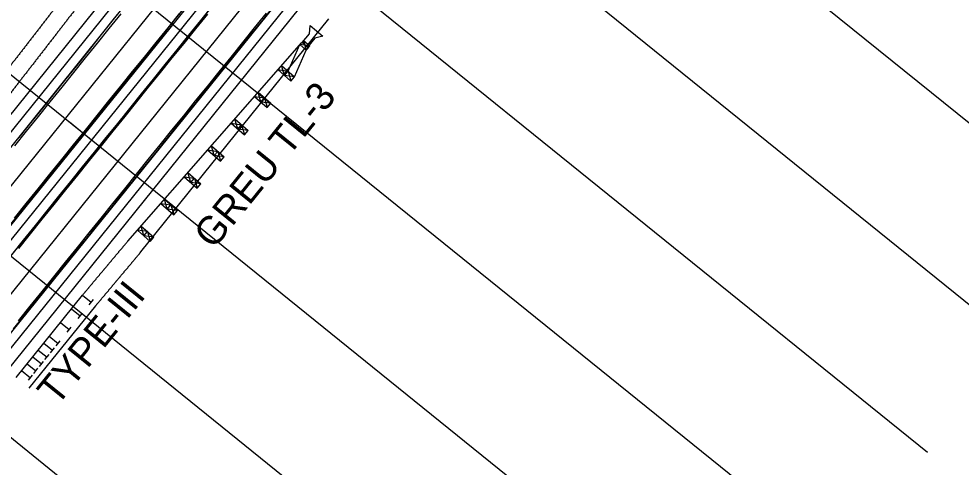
# Model space of a CAD drawing. Extents: x 2293233 to 2294507, y 892788 to 894229.
# Drawn here: x 2293993.2 to 2294160.2, y 893572.2 to 893651.6 of the extents above; entities that cross this region are included whole.
import ezdxf

# ---------------------------------------------------------------- set-up
doc = ezdxf.new("R2010")
doc.units = 0
for name, color, linetype in [('COGO Default Curve', 7, 'Continuous'), ('Prop EOT', 7, 'Continuous'), ('Prop Guardrail', 7, 'Continuous'), ('Prop Guardrail Anchor Unit CELL', 7, 'Continuous'), ('Prop Horizontal Alignment', 7, 'Continuous'), ('Prop Paved Shoulder', 7, 'Continuous'), ('Prop Structure Anchor Unit CELL', 7, 'Continuous'), ('Scratch_Level_4', 7, 'Continuous'), ('Scratch_Level_5', 7, 'Continuous')]:
    doc.layers.add(name, color=color, linetype=linetype)

msp = doc.modelspace()

# ---------------------------------------------------------------- linework, layer by layer
at = {"layer": 'COGO Default Curve'}
for p, q in [((2293758.37, 893332.69), (2294065.5, 893713.27)), ((2293767.71, 893325.15), (2294074.84, 893705.73))]:
    msp.add_line(p, q, dxfattribs=at)
for points in [[(2294153.14, 893810.31), (2294150.2, 893805.46), (2294144.41, 893796.11), (2294138.51, 893786.83), (2294132.51, 893777.61), (2294126.4, 893768.47), (2294120.19, 893759.4), (2294113.87, 893750.39), (2294110.57, 893745.78), (2294107.25, 893741.2), (2294103.51, 893736.09), (2294099.53, 893730.74), (2294095.52, 893725.42), (2294091.47, 893720.12), (2294087.39, 893714.85), (2294083.28, 893709.6), (2294078.73, 893703.85), (2294073.94, 893697.86), (2293868.79, 893443.63)], [(2293934.91, 893558.24), (2293982.19, 893616.89), (2294012.67, 893654.83), (2294024.95, 893670.19), (2294035.75, 893683.75), (2294045.26, 893695.77), (2294053.92, 893706.78), (2294061.7, 893716.77), (2294068.83, 893726.01), (2294075.49, 893734.76), (2294081.7, 893743.02), (2294085.47, 893748.1), (2294089.22, 893753.21), (2294092.74, 893758.07), (2294096.24, 893762.94), (2294099.7, 893767.84), (2294102.95, 893772.49), (2294106.35, 893777.42), (2294109.73, 893782.38), (2294113.08, 893787.36), (2294116.39, 893792.36), (2294119.68, 893797.38), (2294123.12, 893802.7), (2294126.34, 893807.75)], [(2294137.26, 893807.39), (2294131.61, 893798.35), (2294125.85, 893789.36), (2294119.8, 893780.17), (2294113.84, 893771.33), (2294107.78, 893762.55), (2294101.61, 893753.84), (2294095.16, 893744.94), (2294091.39, 893739.84), (2294087.6, 893734.78), (2294083.76, 893729.73), (2294079.69, 893724.45), (2294075.59, 893719.2), (2294071.04, 893713.45), (2294059.17, 893698.61), (2294044.74, 893680.7), (2293954.06, 893568.41)], [(2293932.89, 893536.61), (2294046.75, 893677.72), (2294053.42, 893686.04), (2294059.44, 893693.61), (2294065.01, 893700.68), (2294070.34, 893707.51), (2294075.44, 893714.1), (2294080.29, 893720.46), (2294085.11, 893726.85), (2294089.69, 893733), (2294096.97, 893742.96), (2294103.95, 893752.72), (2294107.4, 893757.63), (2294110.82, 893762.56), (2294114.21, 893767.5), (2294117.58, 893772.47), (2294120.92, 893777.46), (2294124.04, 893782.19), (2294127.32, 893787.21), (2294130.39, 893791.98), (2294133.61, 893797.04), (2294136.62, 893801.84), (2294139.78, 893806.94)], [(2294022.82, 893653.91), (2294020.74, 893651.3), (2294018.65, 893648.7), (2294016.57, 893646.1), (2294014.48, 893643.5), (2294012.39, 893640.9), (2294010.31, 893638.3), (2294008.22, 893635.7), (2294006.13, 893633.1), (2294004.04, 893630.5), (2294001.95, 893627.9), (2293999.86, 893625.3), (2293997.77, 893622.7), (2293995.69, 893620.1), (2293993.6, 893617.51), (2293991.5, 893614.91)], [(2293991.98, 893609.83), (2293994.07, 893612.42), (2293996.17, 893615.01), (2293998.26, 893617.61), (2294000.35, 893620.2), (2294002.45, 893622.8), (2294004.54, 893625.39), (2294006.63, 893627.99), (2294008.73, 893630.58), (2294010.82, 893633.17), (2294012.91, 893635.77), (2294015.01, 893638.36), (2294017.1, 893640.96), (2294019.2, 893643.55), (2294021.29, 893646.15), (2294023.38, 893648.74), (2294025.48, 893651.33), (2294027.57, 893653.93)], [(2293992.31, 893596.7), (2293994.41, 893599.3), (2293996.5, 893601.89), (2293998.59, 893604.49), (2294000.69, 893607.08), (2294002.78, 893609.68), (2294004.87, 893612.27), (2294006.97, 893614.86), (2294009.06, 893617.46), (2294011.15, 893620.05), (2294013.25, 893622.65), (2294015.34, 893625.24), (2294017.44, 893627.84), (2294019.53, 893630.43), (2294021.62, 893633.02), (2294023.72, 893635.62), (2294025.81, 893638.21), (2294027.9, 893640.81), (2294030, 893643.4), (2294032.09, 893646), (2294034.18, 893648.59), (2294036.28, 893651.18), (2294038.37, 893653.78)], [(2294012.02, 893654.02), (2294009.93, 893651.42), (2294007.85, 893648.82), (2294005.76, 893646.22), (2294003.68, 893643.62), (2294001.59, 893641.02), (2293999.5, 893638.42), (2293997.42, 893635.82), (2293995.33, 893633.22), (2293993.24, 893630.63)], [(2294021.72, 893652.65), (2294019.62, 893650.05), (2294017.53, 893647.46), (2294015.44, 893644.86), (2294013.34, 893642.27), (2294011.25, 893639.67), (2294009.16, 893637.08), (2294007.06, 893634.49), (2294004.97, 893631.89), (2294002.87, 893629.3), (2294000.78, 893626.7), (2293998.69, 893624.11), (2293996.59, 893621.51), (2293994.5, 893618.92), (2293992.41, 893616.33)], [(2294011.3, 893652.48), (2294009.21, 893649.89), (2294007.12, 893647.29), (2294005.02, 893644.7), (2294002.93, 893642.1), (2294000.84, 893639.51), (2293998.74, 893636.91), (2293996.65, 893634.32), (2293994.55, 893631.73), (2293992.46, 893629.13)], [(2293993.16, 893598.15), (2293995.25, 893600.75), (2293997.35, 893603.34), (2293999.44, 893605.94), (2294001.53, 893608.53), (2294003.63, 893611.12), (2294005.72, 893613.72), (2294007.82, 893616.31), (2294009.91, 893618.91), (2294012, 893621.5), (2294014.1, 893624.1), (2294016.19, 893626.69), (2294018.28, 893629.28), (2294020.38, 893631.88), (2294022.47, 893634.47), (2294024.56, 893637.07), (2294026.66, 893639.66), (2294028.75, 893642.26), (2294030.85, 893644.85), (2294032.94, 893647.44), (2294035.03, 893650.04), (2294037.13, 893652.63)], [(2293993.22, 893610.96), (2293995.31, 893613.55), (2293997.4, 893616.15), (2293999.5, 893618.74), (2294001.59, 893621.34), (2294003.68, 893623.93), (2294005.78, 893626.53), (2294007.87, 893629.12), (2294009.96, 893631.71), (2294012.06, 893634.31), (2294014.15, 893636.9), (2294016.25, 893639.5), (2294018.34, 893642.09), (2294020.43, 893644.69), (2294022.53, 893647.28), (2294024.62, 893649.87), (2294026.71, 893652.47)]]:
    msp.add_lwpolyline(points, dxfattribs=at)
at = {"layer": 'Prop EOT'}
for p, q in [((2293753.7, 893336.46), (2294060.83, 893717.04)), ((2293753.7, 893336.46), (2294060.83, 893717.04)), ((2293772.37, 893321.38), (2294079.51, 893701.97))]:
    msp.add_line(p, q, dxfattribs=at)
at = {"layer": 'Prop Guardrail'}
for points in [[(2294010.25, 893662.32), (2294009.84, 893661.79), (2294009.42, 893661.25), (2294009.01, 893660.72), (2294008.6, 893660.19), (2294008.18, 893659.65), (2294007.77, 893659.12), (2294007.35, 893658.58), (2294006.94, 893658.05), (2294006.53, 893657.51), (2294006.11, 893656.98), (2294005.7, 893656.45), (2294005.29, 893655.91), (2294004.87, 893655.38), (2294004.46, 893654.84), (2294004.04, 893654.31), (2294003.63, 893653.77), (2294003.22, 893653.24), (2294002.8, 893652.71), (2294002.39, 893652.17), (2294001.97, 893651.64), (2294001.56, 893651.1), (2294001.15, 893650.57), (2294000.73, 893650.03), (2294000.32, 893649.5), (2293999.91, 893648.97), (2293999.49, 893648.43), (2293999.08, 893647.9), (2293998.66, 893647.36), (2293998.25, 893646.83), (2293997.84, 893646.29), (2293997.42, 893645.76), (2293997.01, 893645.23), (2293996.59, 893644.69), (2293996.18, 893644.16), (2293995.77, 893643.62), (2293995.35, 893643.09), (2293994.94, 893642.55), (2293994.53, 893642.02), (2293994.11, 893641.49), (2293993.7, 893640.95), (2293993.28, 893640.42), (2293992.87, 893639.88), (2293992.46, 893639.35), (2293992.04, 893638.81), (2293991.63, 893638.28), (2293991.22, 893637.75), (2293990.8, 893637.21), (2293990.39, 893636.68), (2293989.97, 893636.14), (2293989.56, 893635.61), (2293989.15, 893635.07), (2293988.73, 893634.54), (2293988.32, 893634.01), (2293987.9, 893633.47), (2293987.49, 893632.94), (2293987.08, 893632.4), (2293986.66, 893631.87), (2293986.25, 893631.33), (2293985.84, 893630.8), (2293985.42, 893630.27), (2293985.01, 893629.73), (2293984.59, 893629.2), (2293984.18, 893628.66), (2293983.77, 893628.13), (2293983.35, 893627.59), (2293982.94, 893627.06), (2293982.53, 893626.52), (2293982.11, 893625.99), (2293981.7, 893625.46), (2293981.28, 893624.92), (2293980.87, 893624.39), (2293980.46, 893623.85), (2293980.04, 893623.32), (2293979.63, 893622.78)], [(2294004.53, 893602.69), (2294004.64, 893602.82), (2294004.75, 893602.95), (2294004.86, 893603.08), (2294004.97, 893603.21), (2294005.07, 893603.33), (2294005.18, 893603.46), (2294005.29, 893603.59), (2294005.4, 893603.72), (2294005.51, 893603.85), (2294005.62, 893603.98), (2294005.73, 893604.11), (2294005.84, 893604.24), (2294005.94, 893604.37), (2294006.05, 893604.5), (2294006.16, 893604.63), (2294006.27, 893604.76), (2294006.38, 893604.89), (2294006.49, 893605.02), (2294006.6, 893605.15), (2294006.71, 893605.27), (2294006.81, 893605.4), (2294006.92, 893605.53), (2294007.03, 893605.66), (2294007.14, 893605.79), (2294007.25, 893605.92), (2294007.36, 893606.05), (2294007.47, 893606.18), (2294007.57, 893606.31), (2294007.68, 893606.44), (2294007.79, 893606.57), (2294007.9, 893606.7), (2294008.01, 893606.83), (2294008.12, 893606.96), (2294008.23, 893607.09), (2294008.34, 893607.21), (2294008.44, 893607.34), (2294008.55, 893607.47), (2294008.66, 893607.6), (2294008.77, 893607.73), (2294008.88, 893607.86), (2294008.99, 893607.99), (2294009.1, 893608.12), (2294009.21, 893608.25), (2294009.31, 893608.38), (2294009.42, 893608.51), (2294009.53, 893608.64), (2294009.64, 893608.77), (2294009.75, 893608.9), (2294009.86, 893609.03), (2294009.97, 893609.15), (2294010.08, 893609.28), (2294010.18, 893609.41), (2294010.29, 893609.54), (2294010.4, 893609.67), (2294010.51, 893609.8), (2294010.62, 893609.93), (2294010.73, 893610.06), (2294010.84, 893610.19), (2294010.94, 893610.32), (2294011.05, 893610.45), (2294011.16, 893610.58), (2294011.27, 893610.71), (2294011.38, 893610.84), (2294011.49, 893610.97), (2294011.6, 893611.09), (2294011.71, 893611.22), (2294011.81, 893611.35), (2294011.92, 893611.48), (2294012.03, 893611.61), (2294012.14, 893611.74), (2294012.25, 893611.87), (2294012.36, 893612), (2294012.58, 893612.26)]]:
    msp.add_spline(points, degree=3, dxfattribs=at)
at = {"layer": 'Prop Guardrail Anchor Unit CELL'}
for p, q in [((2294044.77, 893648.98), (2294044.87, 893650.43)), ((2294044.87, 893650.43), (2294047.11, 893648.54)), ((2294043.45, 893647.41), (2294044.77, 893648.98)), ((2294047.11, 893648.54), (2294045.7, 893648.19)), ((2294012.58, 893612.26), (2294043.37, 893647.44)), ((2294040.96, 893642.36), (2294043.04, 893647.06)), ((2294043.04, 893647.06), (2294044.17, 893646.07)), ((2294044.83, 893646.83), (2294043.04, 893647.06)), ((2294043.91, 893647.02), (2294043.45, 893647.41)), ((2294043.7, 893647.81), (2294044.83, 893646.83)), ((2294043.7, 893647.81), (2294044.17, 893646.07)), ((2294044.38, 893646.62), (2294043.91, 893647.02)), ((2294045.7, 893648.19), (2294044.38, 893646.62)), ((2294042.12, 893641.36), (2294044.17, 893646.07)), ((2294044.17, 893646.07), (2294044.83, 893646.83)), ((2294044.17, 893646.07), (2294044.5, 893646.45)), ((2294039.15, 893642.62), (2294041.46, 893640.6)), ((2294039.15, 893642.62), (2294040.96, 893642.36)), ((2294039.81, 893643.37), (2294042.12, 893641.36)), ((2294040.3, 893641.61), (2294039.81, 893643.37)), ((2294040.3, 893641.61), (2294040.96, 893642.36)), ((2294040.96, 893642.36), (2294041.46, 893640.6)), ((2294042.12, 893641.36), (2294040.3, 893641.61)), ((2294041.46, 893640.6), (2294042.12, 893641.36)), ((2294035.66, 893638.63), (2294037.92, 893636.66)), ((2294036.13, 893636.89), (2294035.66, 893638.63)), ((2294035, 893637.88), (2294037.26, 893635.9)), ((2294035, 893637.88), (2294036.79, 893637.64)), ((2294036.13, 893636.89), (2294036.79, 893637.64)), ((2294037.92, 893636.66), (2294036.13, 893636.89)), ((2294036.79, 893637.64), (2294037.26, 893635.9)), ((2294037.26, 893635.9), (2294037.92, 893636.66)), ((2294031.51, 893633.89), (2294033.87, 893631.82)), ((2294032.03, 893632.1), (2294031.51, 893633.89)), ((2294030.85, 893633.14), (2294033.21, 893631.07)), ((2294030.85, 893633.14), (2294032.69, 893632.86)), ((2294032.03, 893632.1), (2294032.69, 893632.86)), ((2294033.87, 893631.82), (2294032.03, 893632.1)), ((2294032.69, 893632.86), (2294033.21, 893631.07)), ((2294033.21, 893631.07), (2294033.87, 893631.82)), ((2294026.7, 893628.4), (2294027.36, 893629.15)), ((2294027.36, 893629.15), (2294029.64, 893627.15)), ((2294027.84, 893627.4), (2294027.36, 893629.15)), ((2294026.7, 893628.4), (2294028.98, 893626.4)), ((2294026.7, 893628.4), (2294028.5, 893628.15)), ((2294027.84, 893627.4), (2294028.5, 893628.15)), ((2294029.64, 893627.15), (2294027.84, 893627.4)), ((2294028.5, 893628.15), (2294028.98, 893626.4)), ((2294028.98, 893626.4), (2294029.64, 893627.15)), ((2294022.55, 893623.65), (2294024.84, 893621.65)), ((2294022.55, 893623.65), (2294024.36, 893623.4)), ((2294023.21, 893624.41), (2294025.5, 893622.4)), ((2294023.7, 893622.65), (2294023.21, 893624.41)), ((2294023.7, 893622.65), (2294024.36, 893623.4)), ((2294025.5, 893622.4), (2294023.7, 893622.65)), ((2294024.36, 893623.4), (2294024.84, 893621.65)), ((2294024.84, 893621.65), (2294025.5, 893622.4)), ((2294018.4, 893618.91), (2294020.7, 893616.9)), ((2294018.4, 893618.91), (2294020.21, 893618.66)), ((2294019.06, 893619.67), (2294021.36, 893617.66)), ((2294019.55, 893617.91), (2294019.06, 893619.67)), ((2294019.55, 893617.91), (2294020.21, 893618.66)), ((2294020.21, 893618.66), (2294020.7, 893616.9)), ((2294021.36, 893617.66), (2294019.55, 893617.91)), ((2294020.7, 893616.9), (2294021.36, 893617.66)), ((2294014.25, 893614.17), (2294014.91, 893614.92)), ((2294014.25, 893614.17), (2294016.51, 893612.2)), ((2294016.04, 893613.94), (2294014.25, 893614.17)), ((2294014.91, 893614.92), (2294017.17, 893612.95)), ((2294014.91, 893614.92), (2294016.04, 893613.94)), ((2294015.38, 893613.18), (2294014.91, 893614.92)), ((2294015.38, 893613.18), (2294016.04, 893613.94)), ((2294016.04, 893613.94), (2294016.51, 893612.2)), ((2294017.17, 893612.95), (2294015.38, 893613.18)), ((2294016.51, 893612.2), (2294017.17, 893612.95))]:
    msp.add_line(p, q, dxfattribs=at)
at = {"layer": 'Prop Horizontal Alignment'}
for p, q in [((2293763.04, 893328.92), (2294070.17, 893709.5)), ((2293763.04, 893328.92), (2294070.17, 893709.5)), ((2294006.14, 893630.16), (2294002.25, 893633.3))]:
    msp.add_line(p, q, dxfattribs=at)
at = {"layer": 'Prop Paved Shoulder'}
for p, q in [((2293752.14, 893337.71), (2294059.27, 893718.29)), ((2293773.93, 893320.13), (2294081.06, 893700.71))]:
    msp.add_line(p, q, dxfattribs=at)
at = {"layer": 'Prop Structure Anchor Unit CELL'}
for p, q in [((2293992.76, 893588.1), (2294004.53, 893602.69)), ((2294004.53, 893602.69), (2294006.09, 893601.43)), ((2294005.73, 893600.99), (2294006.45, 893601.88)), ((2294002.57, 893600.26), (2294004.12, 893599)), ((2294003.76, 893598.55), (2294004.48, 893599.45)), ((2294000.61, 893597.82), (2294002.16, 893596.57)), ((2294001.8, 893596.12), (2294002.52, 893597.01)), ((2293998.64, 893595.39), (2294000.2, 893594.14)), ((2293997.66, 893594.18), (2293999.22, 893592.92)), ((2293999.84, 893593.69), (2294000.56, 893594.58)), ((2293996.68, 893592.96), (2293998.24, 893591.7)), ((2293997.88, 893591.26), (2293998.6, 893592.15)), ((2293998.86, 893592.47), (2293999.58, 893593.37)), ((2293994.72, 893590.53), (2293996.27, 893589.27)), ((2293995.7, 893591.74), (2293997.26, 893590.49)), ((2293996.9, 893590.04), (2293997.62, 893590.93)), ((2293993.74, 893589.31), (2293995.29, 893588.06)), ((2293994.93, 893587.61), (2293995.65, 893588.5)), ((2293995.91, 893588.83), (2293996.63, 893589.72))]:
    msp.add_line(p, q, dxfattribs=at)
at = {"layer": 'Scratch_Level_4'}
for p, q in [((2293952.21, 893802.18), (2294185.67, 893613.78)), ((2293708.32, 893261.12), (2294130.82, 893784.65)), ((2293936.51, 893782.73), (2294169.97, 893594.32)), ((2293920.81, 893763.27), (2294154.27, 893574.87)), ((2293905.11, 893743.82), (2294138.57, 893555.41)), ((2293889.41, 893724.36), (2294122.87, 893535.96)), ((2293873.71, 893704.91), (2294107.17, 893516.5)), ((2293858.01, 893685.45), (2294091.47, 893497.05))]:
    msp.add_line(p, q, dxfattribs=at)
at = {"layer": 'Scratch_Level_5'}
for p, q in [((2294014.87, 893610.33), (2294048.19, 893651.62)), ((2293995.09, 893586.21), (2294006.87, 893600.8))]:
    msp.add_line(p, q, dxfattribs=at)
for points in [[(2294007.88, 893664.16), (2294007.47, 893663.63), (2294007.05, 893663.09), (2294006.64, 893662.56), (2294006.22, 893662.02), (2294005.81, 893661.49), (2294005.4, 893660.95), (2294004.98, 893660.42), (2294004.57, 893659.89), (2294004.15, 893659.35), (2294003.74, 893658.82), (2294003.33, 893658.28), (2294002.91, 893657.75), (2294002.5, 893657.21), (2294002.09, 893656.68), (2294001.67, 893656.15), (2294001.26, 893655.61), (2294000.84, 893655.08), (2294000.43, 893654.54), (2294000.02, 893654.01), (2293999.6, 893653.47), (2293999.19, 893652.94), (2293998.78, 893652.41), (2293998.36, 893651.87), (2293997.95, 893651.34), (2293997.53, 893650.8), (2293997.12, 893650.27), (2293996.71, 893649.73), (2293996.29, 893649.2), (2293995.88, 893648.67), (2293995.46, 893648.13), (2293995.05, 893647.6), (2293994.64, 893647.06), (2293994.22, 893646.53), (2293993.81, 893645.99), (2293993.4, 893645.46), (2293992.98, 893644.93), (2293992.57, 893644.39), (2293992.15, 893643.86), (2293991.74, 893643.32), (2293991.33, 893642.79), (2293990.91, 893642.25), (2293990.5, 893641.72), (2293990.08, 893641.19), (2293989.67, 893640.65), (2293989.26, 893640.12), (2293988.84, 893639.58), (2293988.43, 893639.05), (2293988.02, 893638.51), (2293987.6, 893637.98), (2293987.19, 893637.44), (2293986.77, 893636.91), (2293986.36, 893636.38), (2293985.95, 893635.84), (2293985.53, 893635.31), (2293985.12, 893634.77), (2293984.71, 893634.24), (2293984.29, 893633.7), (2293983.88, 893633.17), (2293983.46, 893632.64), (2293983.05, 893632.1), (2293982.64, 893631.57), (2293982.22, 893631.03), (2293981.81, 893630.5), (2293981.39, 893629.96), (2293980.98, 893629.43), (2293980.57, 893628.9), (2293980.15, 893628.36), (2293979.74, 893627.83), (2293979.33, 893627.29), (2293978.91, 893626.76), (2293978.5, 893626.22), (2293978.08, 893625.69), (2293977.67, 893625.16), (2293977.26, 893624.62)], [(2294006.83, 893600.76), (2294006.94, 893600.89), (2294007.04, 893601.02), (2294007.15, 893601.15), (2294007.26, 893601.28), (2294007.37, 893601.4), (2294007.48, 893601.53), (2294007.59, 893601.66), (2294007.7, 893601.79), (2294007.81, 893601.92), (2294007.91, 893602.05), (2294008.02, 893602.18), (2294008.13, 893602.31), (2294008.24, 893602.44), (2294008.35, 893602.57), (2294008.46, 893602.7), (2294008.57, 893602.83), (2294008.68, 893602.96), (2294008.78, 893603.09), (2294008.89, 893603.22), (2294009, 893603.34), (2294009.11, 893603.47), (2294009.22, 893603.6), (2294009.33, 893603.73), (2294009.44, 893603.86), (2294009.55, 893603.99), (2294009.65, 893604.12), (2294009.76, 893604.25), (2294009.87, 893604.38), (2294009.98, 893604.51), (2294010.09, 893604.64), (2294010.2, 893604.77), (2294010.31, 893604.9), (2294010.41, 893605.03), (2294010.52, 893605.16), (2294010.63, 893605.28), (2294010.74, 893605.41), (2294010.85, 893605.54), (2294010.96, 893605.67), (2294011.07, 893605.8), (2294011.18, 893605.93), (2294011.28, 893606.06), (2294011.39, 893606.19), (2294011.5, 893606.32), (2294011.61, 893606.45), (2294011.72, 893606.58), (2294011.83, 893606.71), (2294011.94, 893606.84), (2294012.05, 893606.97), (2294012.15, 893607.1), (2294012.26, 893607.22), (2294012.37, 893607.35), (2294012.48, 893607.48), (2294012.59, 893607.61), (2294012.7, 893607.74), (2294012.81, 893607.87), (2294012.92, 893608), (2294013.02, 893608.13), (2294013.13, 893608.26), (2294013.24, 893608.39), (2294013.35, 893608.52), (2294013.46, 893608.65), (2294013.57, 893608.78), (2294013.68, 893608.91), (2294013.78, 893609.04), (2294013.89, 893609.16), (2294014, 893609.29), (2294014.11, 893609.42), (2294014.22, 893609.55), (2294014.33, 893609.68), (2294014.44, 893609.81), (2294014.55, 893609.94), (2294014.65, 893610.07), (2294014.87, 893610.33)]]:
    msp.add_spline(points, degree=3, dxfattribs=at)

# ---------------------------------------------------------------- texts
at = {"layer": 'Prop Guardrail Anchor Unit CELL'}
msp.add_text('GREU TL-3', height=5, rotation=51.0748, dxfattribs=at).set_placement((2294027.76, 893610.63))
at = {"layer": 'Prop Structure Anchor Unit CELL'}
msp.add_text('TYPE-III', height=5, rotation=51.0748, dxfattribs=at).set_placement((2294000.04, 893582.88))

doc.saveas('drawing.dxf')
